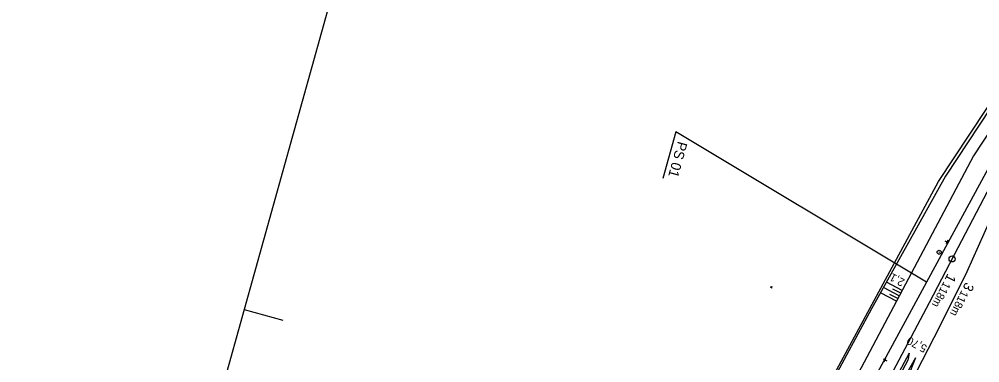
# Model space of a CAD drawing. Extents: x -795094 to -794639, y -1135368 to -1134681.
# Drawn here: x -795037.8 to -794797.7, y -1134896.9 to -1134811 of the extents above; entities that cross this region are included whole.
import ezdxf

# ---------------------------------------------------------------- set-up
doc = ezdxf.new("R2010")
doc.units = 0
for name, color, linetype in [('0381KM005-009P - Vrstva 1', 7, 'Continuous'), ('0381KM005-009P - Vrstva 48', 7, 'Continuous'), ('0381KM005-009P - Vrstva 49', 7, 'Continuous'), ('0381KM005-009P - Vrstva 7', 7, 'Continuous'), ('formát', 7, 'Continuous'), ('hran DP - hran DP', 7, 'Continuous'), ('PSR_C2_1_trasa_Strunkovice - Kabelová trasa', 7, 'Continuous'), ('SOPS', 7, 'Continuous')]:
    doc.layers.add(name, color=color, linetype=linetype)

msp = doc.modelspace()

# ---------------------------------------------------------------- linework, layer by layer
at = {"layer": '0381KM005-009P - Vrstva 1'}
for points in [[(-794788.58, -1134840.28), (-794803.19, -1134868.16), (-794810.38, -1134881.86), (-794818.66, -1134897.6), (-794826.62, -1134912.5), (-794834.33, -1134926.85), (-794861.92, -1134977.99)], [(-794786.96, -1134841.36), (-794793.84, -1134858.32), (-794800.91, -1134874.12), (-794807.73, -1134887.87), (-794826.52, -1134924.29), (-794833.34, -1134937.13), (-794839.37, -1134947.86), (-794840.75, -1134950.16), (-794846.08, -1134958.61), (-794850.88, -1134965.55), (-794860.1, -1134978.74)]]:
    msp.add_lwpolyline(points, dxfattribs=at)
at = {"layer": '0381KM005-009P - Vrstva 48'}
for p, q in [((-794817.11, -1134878.83), (-794821.04, -1134876.75)), ((-794818.52, -1134881.48), (-794822.5, -1134879.37)), ((-794817.81, -1134880.16), (-794821.77, -1134878.06)), ((-794818.17, -1134880.82), (-794820.15, -1134879.77)), ((-794817.46, -1134879.49), (-794819.43, -1134878.45))]:
    msp.add_line(p, q, dxfattribs=at)
at = {"layer": '0381KM005-009P - Vrstva 49'}
for p, q in [((-794781.56, -1134812.71), (-794806.26, -1134850.22)), ((-794779.34, -1134814.68), (-794799.26, -1134845.15)), ((-794799.26, -1134845.15), (-794840.65, -1134923.24)), ((-794806.26, -1134850.22), (-794824.73, -1134883.39)), ((-794849.62, -1134877.9), (-794850.1, -1134878.05)), ((-794849.94, -1134877.74), (-794849.79, -1134878.21)), ((-794824.73, -1134883.39), (-794837.68, -1134907.33))]:
    msp.add_line(p, q, dxfattribs=at)
for points in [[(-794815.37, -1134894.44), (-794815.67, -1134896.21), (-794830.44, -1134923.9), (-794846.52, -1134953.51), (-794848.28, -1134955.61)], [(-794815.37, -1134894.44), (-794830.99, -1134923.68), (-794848.28, -1134955.61)], [(-794813.73, -1134895.61), (-794815.7, -1134900.49), (-794822, -1134912.52), (-794829.49, -1134927.01), (-794835.62, -1134938.73), (-794838.1, -1134942.66)], [(-794813.73, -1134895.61), (-794816.27, -1134900.06), (-794822.55, -1134912.27), (-794829.83, -1134926.6), (-794836.24, -1134938.45), (-794838.1, -1134942.66)]]:
    msp.add_lwpolyline(points, dxfattribs=at)
at = {"layer": '0381KM005-009P - Vrstva 7'}
for p, q in [((-794805.45, -1134866.91), (-794806.34, -1134866.45)), ((-794805.66, -1134866.24), (-794806.13, -1134867.13)), ((-794807.82, -1134869.17), (-794807.87, -1134869.26)), ((-794821.83, -1134895.92), (-794820.94, -1134896.39)), ((-794821.62, -1134896.6), (-794821.15, -1134895.71))]:
    msp.add_line(p, q, dxfattribs=at)
for centre, radius in [((-794807.84, -1134869.22), 0.5), ((-794804.63, -1134870.91), 0.75)]:
    msp.add_circle(centre, radius, dxfattribs=at)
at = {"layer": 'formát'}
for p, q in [((-794925.31, -1134681.22), (-794981.56, -1134883.54)), ((-794981.56, -1134883.54), (-795037.81, -1135085.87)), ((-794981.56, -1134883.54), (-794971.92, -1134886.22))]:
    msp.add_line(p, q, dxfattribs=at)
at = {"layer": 'hran DP - hran DP'}
for p, q in [((-794808.02, -1134851.51), (-794775.44, -1134802.2)), ((-794834.03, -1134899.62), (-794808.02, -1134851.51))]:
    msp.add_line(p, q, dxfattribs=at)
at = {"layer": 'PSR_C2_1_trasa_Strunkovice - Kabelová trasa'}
msp.add_lwpolyline([(-794859.57, -1134988.66), (-794835.3, -1134945.55), (-794845.51, -1134940.37), (-794776.44, -1134813), (-794772.18, -1134815.08)], dxfattribs=at)
at = {"layer": 'SOPS'}
msp.add_lwpolyline([(-794810.98, -1134876.68), (-794873.65, -1134839.13), (-794876.9, -1134850.82)], dxfattribs=at)

# ---------------------------------------------------------------- texts
at = {"layer": '0381KM005-009P - Vrstva 1'}
for s, height, rotation, p in [('1', 2.5, 242.3222, (-794805.68, -1134874.39)), ('118m', 2, 242.2272, (-794806.66, -1134876.42)), ('3', 2.5, 243.6203, (-794801.22, -1134876.56)), ('118m', 2, 243.6203, (-794802.23, -1134878.61)), ('5,70', 2, 152.2272, (-794810.68, -1134892.67))]:
    msp.add_text(s, height=height, rotation=rotation, dxfattribs=at).set_placement(p)
at = {"layer": '0381KM005-009P - Vrstva 48'}
msp.add_text('2,1', height=2, rotation=152.0771, dxfattribs=at).set_placement((-794816.27, -1134876.14))
at = {"layer": 'SOPS'}
msp.add_text('PS 01', height=2.5, rotation=254.4625, dxfattribs=at).set_placement((-794873.15, -1134841.35))

doc.saveas('drawing.dxf')
